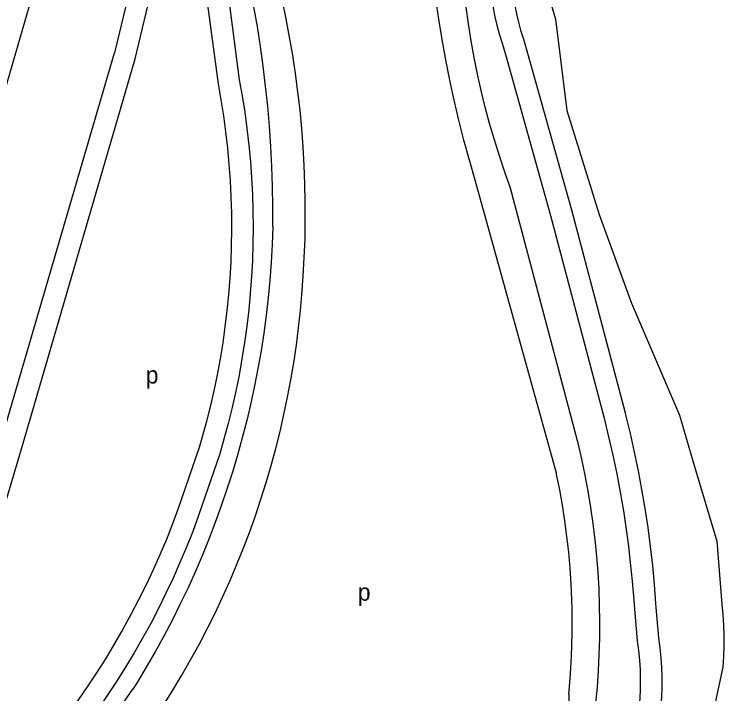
# Model space of a CAD drawing. Extents: x 159045 to 160918, y 380454 to 382516.
# Drawn here: x 160558.4 to 160722.8, y 381185.5 to 381342.9 of the extents above; entities that cross this region are included whole.
import ezdxf

# ---------------------------------------------------------------- set-up
doc = ezdxf.new("R2010")
doc.units = 0
doc.layers.add('BLT_Basislijn', color=7, linetype='Continuous')
doc.layers.add('BLT_Centroide', color=7, linetype='Continuous')

msp = doc.modelspace()

# ---------------------------------------------------------------- linework, layer by layer
at = {"layer": 'BLT_Basislijn'}
for p, q in [((160599.42, 381373.29), (160605.6, 381326.82)), ((160604.38, 381373.88), (160610.51, 381327.75)), ((160588.64, 381363.3), (160581.56, 381334)), ((160586.36, 381332.61), (160593.52, 381362.21)), ((160676.38, 381337.13), (160677.31, 381333.89)), ((160671.66, 381335.46), (160672.5, 381332.54)), ((160555.45, 381244.39), (160581.56, 381334)), ((160677.31, 381333.89), (160687.47, 381297.6)), ((160560.24, 381242.97), (160586.36, 381332.61)), ((160672.5, 381332.54), (160682.66, 381296.25)), ((160683.99, 381236.55), (160665.14, 381304.51)), ((160689.21, 381242.9), (160673.35, 381302.64)), ((160687.47, 381297.6), (160699.89, 381250.53)), ((160682.66, 381296.25), (160695.04, 381249.29)), ((160697.84, 381285.67), (160700, 381279.78)), ((160699.89, 381250.53), (160700, 381250.08)), ((160526.31, 381128.51), (160560.24, 381242.97)), ((160601.18, 381242.5), (160596.37, 381228.42)), ((160605.97, 381241.06), (160601.09, 381226.76)), ((160707.05, 381205.47), (160707.68, 381198.41)), ((160702.06, 381205.15), (160702.73, 381197.66)), ((160569.62, 381163.37), (160585.85, 381186.52))]:
    msp.add_line(p, q, dxfattribs=at)
for points in [[(160673.35, 381302.64), (160672.03, 381306.35), (160670.78, 381310.08), (160669.61, 381313.83), (160668.52, 381317.61), (160667.51, 381321.41), (160666.57, 381325.23), (160665.71, 381329.07), (160664.92, 381332.92), (160664.22, 381336.79), (160663.59, 381340.68), (160663.05, 381344.57), (160662.58, 381348.48), (160662.19, 381352.39), (160661.89, 381356.32), (160661.66, 381360.24), (160661.51, 381364.17), (160661.44, 381368.11), (160661.46, 381372.04), (160661.55, 381375.97), (160661.72, 381379.9), (160661.97, 381383.83), (160662.3, 381387.75), (160662.53, 381390.01)], [(160532.31, 381242.9), (160565.52, 381357.53), (160570.85, 381376.71)], [(160665.14, 381304.51), (160663.83, 381309.1), (160662.58, 381313.71), (160661.42, 381318.34), (160660.33, 381322.99), (160659.33, 381327.65), (160658.4, 381332.33), (160657.55, 381337.03), (160656.77, 381341.74), (160656.08, 381346.47), (160655.47, 381351.2), (160654.93, 381355.95), (160654.48, 381360.7), (160654.1, 381365.46), (160653.81, 381370.22), (160653.59, 381374.99), (160653.58, 381375.45)], [(160680.65, 381367.73), (160681.02, 381351.28), (160683.82, 381341.75), (160686.44, 381320.62), (160693.91, 381296.51), (160697.84, 381285.67)], [(160625.03, 381278), (160625.35, 381282.26), (160625.58, 381286.53), (160625.74, 381290.81), (160625.81, 381295.09), (160625.81, 381299.36), (160625.72, 381303.64), (160625.56, 381307.91), (160625.31, 381312.18), (160624.99, 381316.45), (160624.58, 381320.71), (160624.1, 381324.96), (160623.53, 381329.2), (160622.89, 381333.43), (160622.17, 381337.64), (160621.37, 381341.84), (160620.49, 381346.03), (160619.53, 381350.2), (160619.02, 381352.29)], [(160618.32, 381293.68), (160618.31, 381298.34), (160618.23, 381303), (160618.07, 381307.65), (160617.83, 381312.3), (160617.51, 381316.95), (160617.1, 381321.6), (160616.62, 381326.23), (160616.06, 381330.85), (160615.42, 381335.47), (160614.7, 381340.07), (160613.9, 381344.66), (160613.03, 381349.24), (160612.86, 381350.05)], [(160668.72, 381350.45), (160668.86, 381348.41), (160669.07, 381346.38), (160669.37, 381344.36), (160669.74, 381342.35), (160670.19, 381340.35), (160670.72, 381338.38), (160671.33, 381336.43), (160671.66, 381335.46)], [(160673.72, 381350.68), (160673.85, 381348.75), (160674.06, 381346.81), (160674.35, 381344.89), (160674.72, 381342.98), (160675.17, 381341.09), (160675.69, 381339.22), (160676.29, 381337.37), (160676.38, 381337.13)], [(160610.51, 381327.75), (160611.18, 381323.98), (160611.78, 381320.21), (160612.29, 381316.42), (160612.73, 381312.62), (160613.09, 381308.81), (160613.36, 381304.99), (160613.56, 381301.18), (160613.68, 381297.35), (160613.71, 381293.53), (160613.67, 381289.7), (160613.55, 381285.88), (160613.34, 381282.06), (160613.06, 381278.25), (160612.7, 381274.44), (160612.25, 381270.64), (160611.73, 381266.85), (160611.13, 381263.08), (160610.45, 381259.31), (160609.69, 381255.57), (160608.86, 381251.83), (160607.94, 381248.12), (160606.95, 381244.43), (160605.97, 381241.06)], [(160605.6, 381326.82), (160606.26, 381323.1), (160606.85, 381319.38), (160607.35, 381315.64), (160607.78, 381311.89), (160608.12, 381308.14), (160608.39, 381304.37), (160608.58, 381300.61), (160608.68, 381296.84), (160608.71, 381293.07), (160608.66, 381289.29), (160608.52, 381285.53), (160608.31, 381281.76), (160608.02, 381278), (160607.65, 381274.24), (160607.19, 381270.5), (160606.66, 381266.77), (160606.05, 381263.04), (160605.36, 381259.34), (160604.59, 381255.64), (160603.75, 381251.97), (160602.82, 381248.31), (160601.82, 381244.67), (160601.18, 381242.5)], [(160618.32, 381293.68), (160618.16, 381289.55), (160617.92, 381285.43), (160617.61, 381281.32), (160617.21, 381277.21), (160616.74, 381273.11), (160616.18, 381269.02), (160615.55, 381264.94), (160614.84, 381260.87), (160614.05, 381256.82), (160613.18, 381252.79), (160612.23, 381248.77), (160611.2, 381244.77), (160610.1, 381240.79), (160608.92, 381236.84), (160607.66, 381232.9), (160606.33, 381229), (160604.92, 381225.12), (160603.44, 381221.26), (160601.89, 381217.44), (160600.25, 381213.65), (160598.55, 381209.89), (160596.77, 381206.16), (160594.93, 381202.47), (160593.01, 381198.82), (160591.02, 381195.2), (160588.96, 381191.62), (160586.83, 381188.09), (160585.85, 381186.52)], [(160700, 381279.78), (160701.41, 381275.94), (160712.5, 381250), (160715.77, 381238.93), (160721.19, 381220.8), (160722.31, 381206.22)], [(160617.37, 381236.52), (160617.9, 381238.34), (160618.97, 381242.27), (160619.96, 381246.22), (160620.87, 381250.19), (160621.71, 381254.17), (160622.46, 381258.17), (160623.14, 381262.18), (160623.74, 381266.21), (160624.26, 381270.25), (160624.7, 381274.29), (160625.03, 381278)], [(160700, 381250.08), (160701.05, 381245.78), (160702.03, 381241.46), (160702.92, 381237.12), (160703.74, 381232.76), (160704.48, 381228.39), (160705.14, 381224.01), (160705.72, 381219.62), (160706.22, 381215.22), (160706.64, 381210.8), (160706.98, 381206.39), (160707.05, 381205.47)], [(160695.04, 381249.29), (160696.09, 381245.03), (160697.06, 381240.75), (160697.96, 381236.46), (160698.77, 381232.15), (160699.51, 381227.82), (160700, 381224.61)], [(160693.49, 381187.01), (160693.75, 381190.8), (160693.93, 381194.59), (160694.04, 381198.38), (160694.06, 381202.18), (160694, 381205.97), (160693.87, 381209.77), (160693.65, 381213.56), (160693.35, 381217.34), (160692.98, 381221.12), (160692.52, 381224.89), (160691.99, 381228.64), (160691.37, 381232.39), (160690.68, 381236.12), (160689.91, 381239.84), (160689.21, 381242.9)], [(160610.89, 381217.76), (160611.42, 381219.06), (160612.87, 381222.86), (160614.24, 381226.7), (160615.54, 381230.55), (160616.76, 381234.44), (160617.37, 381236.52)], [(160687.63, 381204.96), (160687.58, 381207.29), (160687.42, 381210.95), (160687.17, 381214.6), (160686.85, 381218.25), (160686.44, 381221.89), (160685.96, 381225.52), (160685.4, 381229.14), (160684.75, 381232.74), (160684.03, 381236.33), (160683.99, 381236.55)], [(160596.37, 381228.42), (160595.03, 381224.83), (160593.61, 381221.24), (160592.11, 381217.69), (160590.54, 381214.17), (160588.9, 381210.68), (160587.19, 381207.22), (160585.4, 381203.81), (160583.55, 381200.43), (160581.62, 381197.09), (160579.63, 381193.79), (160577.57, 381190.53), (160575.44, 381187.31), (160573.24, 381184.15), (160570.98, 381181.02), (160568.66, 381177.95), (160566.27, 381174.92), (160563.82, 381171.94), (160561.4, 381169.12)], [(160601.09, 381226.76), (160599.71, 381223.08), (160598.28, 381219.45), (160596.76, 381215.85), (160595.18, 381212.28), (160593.52, 381208.74), (160591.79, 381205.24), (160589.98, 381201.77), (160588.11, 381198.34), (160586.17, 381194.95), (160584.16, 381191.6), (160582.08, 381188.29), (160579.93, 381185.03), (160577.72, 381181.81), (160575.44, 381178.64), (160573.09, 381175.51), (160570.69, 381172.43), (160568.22, 381169.41), (160565.69, 381166.43), (160565.16, 381165.83)], [(160700, 381224.61), (160700.6, 381220.27), (160701.12, 381215.92), (160701.56, 381211.55), (160701.92, 381207.18), (160702.06, 381205.15)], [(160603.3, 381200.96), (160604.89, 381204.15), (160606.63, 381207.83), (160608.3, 381211.54), (160609.89, 381215.29), (160610.89, 381217.76)], [(160722.31, 381206.22), (160722.54, 381203.8), (160722.7, 381201.37), (160722.78, 381198.94), (160722.78, 381196.5), (160722.7, 381194.07), (160722.54, 381191.64)], [(160686.89, 381185.35), (160687.21, 381189), (160687.44, 381192.65), (160687.6, 381196.31), (160687.67, 381199.97), (160687.67, 381203.63), (160687.63, 381204.96)], [(160591.33, 381180.4), (160592.95, 381182.86), (160595.11, 381186.31), (160597.2, 381189.8), (160599.23, 381193.33), (160601.18, 381196.9), (160603.07, 381200.51), (160603.3, 381200.96)], [(160702.73, 381197.66), (160703.02, 381195.46), (160703.24, 381193.26), (160703.37, 381191.05), (160703.43, 381188.83), (160703.4, 381186.61), (160703.3, 381184.4), (160703.11, 381182.19), (160702.85, 381179.99), (160702.5, 381177.8), (160702.08, 381175.63), (160701.58, 381173.47), (160701, 381171.33), (160700.67, 381170.23)], [(160707.68, 381198.41), (160707.98, 381196.13), (160708.21, 381193.83), (160708.36, 381191.54), (160708.43, 381189.23), (160708.41, 381186.93), (160708.32, 381184.62), (160708.15, 381182.33), (160707.9, 381180.04), (160707.57, 381177.76), (160707.16, 381175.49), (160706.67, 381173.24), (160706.1, 381171), (160705.45, 381168.75)], [(160722.54, 381191.64), (160720.51, 381182.3), (160717.73, 381176.32), (160712.67, 381170.48), (160704.71, 381166.35)], [(160686.89, 381185.35), (160686.89, 381182.91), (160688.13, 381181.41), (160691.69, 381181.27), (160693.14, 381183.31), (160693.49, 381187.01)]]:
    msp.add_lwpolyline(points, dxfattribs=at)

# ---------------------------------------------------------------- texts
at = {"layer": 'BLT_Centroide'}
for p in [(160588.81, 381257.35), (160637.96, 381207.03)]:
    msp.add_text('p', height=4, dxfattribs=at).set_placement(p)

doc.saveas('drawing.dxf')
